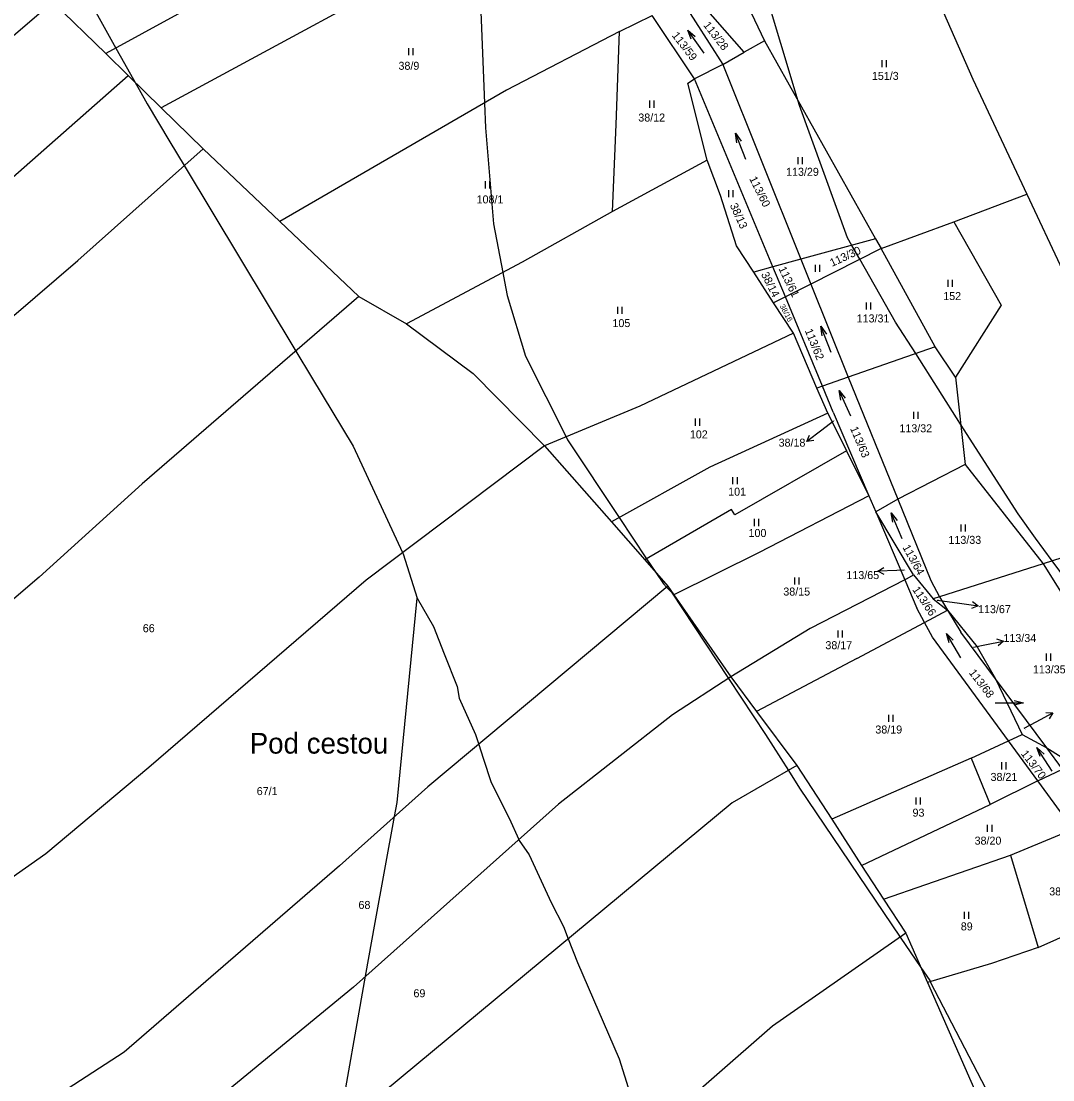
# Model space of a CAD drawing. Extents: x -749173 to -746119, y -1132678 to -1130338.
# Drawn here: x -747589.9 to -747370.7, y -1131323.7 to -1131098.8 of the extents above; entities that cross this region are included whole.
import ezdxf

# ---------------------------------------------------------------- set-up
doc = ezdxf.new("R2010")
doc.units = 0
for name, color, linetype in [('Vrstva 1', 7, 'Continuous'), ('Vrstva 15', 7, 'Continuous'), ('Vrstva 16', 7, 'Continuous'), ('Vrstva 18', 7, 'Continuous'), ('Vrstva 25', 7, 'Continuous'), ('Vrstva 52', 7, 'Continuous'), ('Vrstva 6', 7, 'Continuous')]:
    doc.layers.add(name, color=color, linetype=linetype)

msp = doc.modelspace()

# ---------------------------------------------------------------- linework, layer by layer
at = {"layer": 'Vrstva 1'}
for points in [[(-747407.71, -1131065.71), (-747387.68, -1131111.18)], [(-747583.1, -1131094.79), (-747571.91, -1131105.73)], [(-747449.55, -1131094.47), (-747440.84, -1131108.03)], [(-747446.81, -1131111.05), (-747455.83, -1131097.63)], [(-747571.91, -1131105.73), (-747567.13, -1131110.4)], [(-747440.84, -1131108.03), (-747424.22, -1131149.41)], [(-747567.13, -1131110.4), (-747560.11, -1131117.26)], [(-747430.18, -1131151.04), (-747446.81, -1131111.05)], [(-747387.68, -1131111.18), (-747376.22, -1131135.6)], [(-747560.11, -1131117.26), (-747551.23, -1131125.94)], [(-747551.23, -1131125.94), (-747534.94, -1131141.41)], [(-747376.22, -1131135.6), (-747368.67, -1131151.69)], [(-747534.94, -1131141.41), (-747518.15, -1131157.34)], [(-747424.22, -1131149.41), (-747422.11, -1131154.66)], [(-747427.53, -1131157.41), (-747430.18, -1131151.04)], [(-747422.11, -1131154.66), (-747414.16, -1131174.44)], [(-747518.15, -1131157.34), (-747508, -1131163.09)], [(-747419.66, -1131176.34), (-747427.53, -1131157.41)], [(-747508, -1131163.09), (-747493.84, -1131173.69)], [(-747493.84, -1131173.69), (-747478.68, -1131189)], [(-747414.16, -1131174.44), (-747403.63, -1131200.37)], [(-747417.35, -1131181.9), (-747419.66, -1131176.34)], [(-747417.35, -1131181.9), (-747409.79, -1131199.63)], [(-747478.68, -1131189), (-747464.5, -1131205.17)], [(-747409.79, -1131199.63), (-747408.32, -1131203.08)], [(-747403.63, -1131200.37), (-747396.62, -1131217.65)], [(-747335.3, -1131202.07), (-747372.79, -1131214.07)], [(-747408.32, -1131203.08), (-747402.18, -1131217.46)], [(-747464.5, -1131205.17), (-747457.41, -1131213.25)], [(-747457.41, -1131213.25), (-747452.5, -1131218.84)], [(-747372.79, -1131214.07), (-747366.49, -1131224.14)], [(-747402.18, -1131217.46), (-747399.59, -1131223.53)], [(-747396.62, -1131217.65), (-747394.81, -1131221.1)], [(-747452.5, -1131218.84), (-747451.24, -1131220.66)], [(-747451.24, -1131220.66), (-747439.12, -1131238.12)], [(-747394.81, -1131221.1), (-747393.08, -1131223.94)], [(-747397.95, -1131226.54), (-747399.59, -1131223.53)], [(-747393.08, -1131223.94), (-747390.29, -1131228.61)], [(-747396.26, -1131229.64), (-747397.95, -1131226.54)], [(-747382.92, -1131238.52), (-747390.29, -1131228.61)], [(-747380.11, -1131251.72), (-747396.26, -1131229.64)], [(-747439.12, -1131238.12), (-747433.68, -1131245.43)], [(-747372.02, -1131253.19), (-747382.92, -1131238.52)], [(-747433.68, -1131245.43), (-747425.11, -1131256.95)], [(-747373.91, -1131260.21), (-747380.11, -1131251.72)], [(-747368.67, -1131257.7), (-747372.02, -1131253.19)], [(-747425.11, -1131256.95), (-747417.7, -1131268.35)], [(-747366.42, -1131270.45), (-747373.91, -1131260.21)], [(-747417.7, -1131268.35), (-747411.33, -1131278.16)], [(-747411.33, -1131278.16), (-747406.7, -1131285.28)], [(-747406.7, -1131285.28), (-747401.97, -1131292.55)], [(-747401.97, -1131292.55), (-747397.34, -1131303.04)], [(-747397.34, -1131303.04), (-747384.78, -1131331.55)]]:
    msp.add_lwpolyline(points, dxfattribs=at)
at = {"layer": 'Vrstva 16'}
for p, q in [((-747421.46, -1131187.91), (-747422.95, -1131188.12)), ((-747406.54, -1131216.37), (-747407.87, -1131215.68)), ((-747387.79, -1131222.09), (-747386.61, -1131223)), ((-747382.66, -1131230.03), (-747381.23, -1131230.49)), ((-747372.23, -1131245.7), (-747370.73, -1131245.76))]:
    msp.add_line(p, q, dxfattribs=at)
for points in [[(-747417.31, -1131183.76), (-747419.78, -1131185.67)], [(-747419.78, -1131185.67), (-747422.95, -1131188.12), (-747422.38, -1131186.73)], [(-747403.87, -1131215.51), (-747407.87, -1131215.68), (-747406.6, -1131214.87)], [(-747402.28, -1131215.44), (-747403.87, -1131215.51)], [(-747395.32, -1131221.83), (-747390.57, -1131222.47)], [(-747390.57, -1131222.47), (-747386.61, -1131223), (-747387.99, -1131223.57)], [(-747387.54, -1131231.81), (-747385.15, -1131231.31)], [(-747385.15, -1131231.31), (-747381.23, -1131230.49), (-747382.35, -1131231.49)], [(-747374.26, -1131247.63), (-747370.73, -1131245.76), (-747371.52, -1131247.03)], [(-747376.82, -1131248.99), (-747374.26, -1131247.63)]]:
    msp.add_lwpolyline(points, dxfattribs=at)
at = {"layer": 'Vrstva 25'}
for p, q in [((-747444.8, -1131105.64), (-747448.26, -1131100.74)), ((-747507.59, -1131104.59), (-747507.59, -1131106.09)), ((-747506.59, -1131106.09), (-747506.59, -1131104.59)), ((-747407.03, -1131107.11), (-747407.03, -1131108.61)), ((-747406.03, -1131108.61), (-747406.03, -1131107.11)), ((-747456.4, -1131115.71), (-747456.4, -1131117.21)), ((-747455.4, -1131117.21), (-747455.4, -1131115.71)), ((-747435.9, -1131128.23), (-747438.12, -1131122.65)), ((-747424.87, -1131127.73), (-747424.87, -1131129.23)), ((-747423.87, -1131129.23), (-747423.87, -1131127.73)), ((-747491.31, -1131132.85), (-747491.31, -1131134.35)), ((-747490.31, -1131134.35), (-747490.31, -1131132.85)), ((-747439.62, -1131134.7), (-747439.62, -1131136.2)), ((-747438.62, -1131136.2), (-747438.62, -1131134.7)), ((-747421.18, -1131150.59), (-747421.18, -1131152.09)), ((-747420.18, -1131152.09), (-747420.18, -1131150.59)), ((-747393, -1131153.76), (-747393, -1131155.26)), ((-747392, -1131155.26), (-747392, -1131153.76)), ((-747463.18, -1131159.49), (-747463.18, -1131160.99)), ((-747462.18, -1131160.99), (-747462.18, -1131159.49)), ((-747410.36, -1131158.56), (-747410.36, -1131160.06)), ((-747409.36, -1131160.06), (-747409.36, -1131158.56)), ((-747417.79, -1131169.24), (-747419.97, -1131163.64)), ((-747413.66, -1131182.76), (-747416.14, -1131177.3)), ((-747400.34, -1131181.78), (-747400.34, -1131183.28)), ((-747399.34, -1131183.28), (-747399.34, -1131181.78)), ((-747446.71, -1131183.25), (-747446.71, -1131184.75)), ((-747445.71, -1131184.75), (-747445.71, -1131183.25)), ((-747438.73, -1131195.67), (-747438.73, -1131197.17)), ((-747437.73, -1131197.17), (-747437.73, -1131195.67)), ((-747434.16, -1131204.56), (-747434.16, -1131206.06)), ((-747433.16, -1131206.06), (-747433.16, -1131204.56)), ((-747402.76, -1131208.77), (-747405.04, -1131203.23)), ((-747390.27, -1131205.71), (-747390.27, -1131207.21)), ((-747389.27, -1131207.21), (-747389.27, -1131205.71)), ((-747425.62, -1131217), (-747425.62, -1131218.5)), ((-747424.62, -1131218.5), (-747424.62, -1131217)), ((-747416.41, -1131228.27), (-747416.41, -1131229.77)), ((-747415.41, -1131229.77), (-747415.41, -1131228.27)), ((-747390.28, -1131234.03), (-747393.34, -1131228.87)), ((-747372.14, -1131233.16), (-747372.14, -1131234.66)), ((-747371.14, -1131234.66), (-747371.14, -1131233.16)), ((-747382.96, -1131243.6), (-747376.96, -1131243.6)), ((-747405.61, -1131246.17), (-747405.61, -1131247.67)), ((-747404.61, -1131247.67), (-747404.61, -1131246.17)), ((-747370.85, -1131258.13), (-747374.09, -1131253.07)), ((-747381.65, -1131256.25), (-747381.65, -1131257.75)), ((-747380.65, -1131257.75), (-747380.65, -1131256.25)), ((-747399.85, -1131263.7), (-747399.85, -1131265.2)), ((-747398.85, -1131265.2), (-747398.85, -1131263.7)), ((-747384.64, -1131269.52), (-747384.64, -1131271.02)), ((-747383.64, -1131271.02), (-747383.64, -1131269.52)), ((-747389.54, -1131287.99), (-747389.54, -1131289.49)), ((-747388.54, -1131289.49), (-747388.54, -1131287.99))]:
    msp.add_line(p, q, dxfattribs=at)
for points in [[(-747447.52, -1131102.66), (-747448.26, -1131100.74), (-747446.7, -1131102.08)], [(-747437.84, -1131124.7), (-747438.12, -1131122.65), (-747436.91, -1131124.33)], [(-747419.71, -1131165.69), (-747419.97, -1131163.64), (-747418.78, -1131165.33)], [(-747415.77, -1131179.33), (-747416.14, -1131177.3), (-747414.86, -1131178.91)], [(-747404.74, -1131205.27), (-747405.04, -1131203.23), (-747403.82, -1131204.89)], [(-747392.75, -1131230.85), (-747393.34, -1131228.87), (-747391.89, -1131230.33)], [(-747378.96, -1131243.1), (-747376.96, -1131243.6), (-747378.96, -1131244.1)], [(-747373.43, -1131255.03), (-747374.09, -1131253.07), (-747372.59, -1131254.49)]]:
    msp.add_lwpolyline(points, dxfattribs=at)
at = {"layer": 'Vrstva 52'}
for points in [[(-747492.89, -1131080.86), (-747491.46, -1131116.22), (-747491.25, -1131121.5), (-747489.56, -1131141.87), (-747487.57, -1131152.24), (-747487.21, -1131154.11), (-747486.62, -1131157.12), (-747482.75, -1131170), (-747474.13, -1131187.11), (-747473.81, -1131187.75), (-747462.84, -1131204.25), (-747457, -1131213.01), (-747455.08, -1131215.9), (-747453.44, -1131218.37), (-747452.77, -1131219.06), (-747451.75, -1131220.12), (-747439.63, -1131238.45), (-747431.75, -1131250.37), (-747426.9, -1131257.98), (-747424.5, -1131261.75), (-747403.13, -1131293.36), (-747398.74, -1131299.86), (-747396.87, -1131302.62), (-747396.75, -1131302.86), (-747384.94, -1131325.62)], [(-747577.22, -1131091.12), (-747569.73, -1131104.54), (-747567.91, -1131107.81), (-747565.66, -1131111.84), (-747564.82, -1131113.33), (-747563.12, -1131116.37), (-747558.25, -1131124.47), (-747555.23, -1131129.51), (-747531.54, -1131168.9), (-747528.2, -1131174.44), (-747519.37, -1131189.12), (-747508.83, -1131211.69), (-747508.69, -1131212), (-747505.75, -1131221.37)], [(-747368.81, -1131216.25), (-747370.86, -1131213.45), (-747374.37, -1131208.64), (-747378.12, -1131203.5), (-747390.3, -1131184.42), (-747399.85, -1131169.45), (-747404.12, -1131162.75), (-747411.72, -1131149.41), (-747413.41, -1131146.45), (-747414.31, -1131144.87), (-747424.5, -1131116.75), (-747424.79, -1131115.8), (-747432.19, -1131091.25)], [(-747522.43, -1131334.23), (-747516.7, -1131301.69), (-747514.69, -1131290.25), (-747510.56, -1131267.78), (-747510, -1131264.75), (-747505.75, -1131221.37)], [(-747505.75, -1131221.37), (-747502.31, -1131227.37), (-747500, -1131233.2), (-747497.25, -1131240.12), (-747496.81, -1131242.62), (-747493.37, -1131250.37), (-747492.68, -1131252.43), (-747491.69, -1131255.37), (-747490, -1131260.5), (-747486.19, -1131268.12), (-747484.17, -1131272.64), (-747484.12, -1131272.74), (-747484.06, -1131272.87), (-747481.94, -1131275.87), (-747477.25, -1131286), (-747474.69, -1131291.12), (-747473.65, -1131293.76), (-747471.69, -1131298.75), (-747462.81, -1131319.25), (-747457.56, -1131336.16)]]:
    msp.add_lwpolyline(points, dxfattribs=at)
at = {"layer": 'Vrstva 6'}
for points in [[(-747519.1, -1131076.81), (-747571.91, -1131105.73)], [(-747493.05, -1131080.92), (-747560.11, -1131117.26)], [(-747437.65, -1131091.07), (-747431.95, -1131103.02)], [(-747436.27, -1131105.41), (-747447.06, -1131093.1)], [(-747583.1, -1131094.79), (-747617.7, -1131124.35)], [(-747462.74, -1131101.03), (-747455.83, -1131097.63)], [(-747462.74, -1131101.03), (-747486.76, -1131113.5)], [(-747463.44, -1131120.77), (-747462.74, -1131101.03)], [(-747431.95, -1131103.02), (-747436.27, -1131105.41)], [(-747431.95, -1131103.02), (-747408.38, -1131145.07)], [(-747440.84, -1131108.03), (-747436.27, -1131105.41)], [(-747440.84, -1131108.03), (-747446.81, -1131111.05)], [(-747620.97, -1131157.74), (-747567.13, -1131110.4)], [(-747448.25, -1131112.03), (-747446.81, -1131111.05)], [(-747444.14, -1131128.36), (-747448.25, -1131112.03)], [(-747486.76, -1131113.5), (-747534.94, -1131141.41)], [(-747464.26, -1131139.24), (-747463.44, -1131120.77)], [(-747577.82, -1131149.69), (-747551.23, -1131125.94)], [(-747444.14, -1131128.36), (-747464.26, -1131139.24)], [(-747441.29, -1131135.89), (-747444.14, -1131128.36)], [(-747437.88, -1131146.58), (-747441.29, -1131135.89)], [(-747391.74, -1131141.48), (-747376.22, -1131135.6)], [(-747464.26, -1131139.24), (-747483.41, -1131150.03)], [(-747407.22, -1131147.14), (-747391.74, -1131141.48)], [(-747391.74, -1131141.48), (-747381.7, -1131159.18)], [(-747408.38, -1131145.07), (-747424.22, -1131149.41)], [(-747408.38, -1131145.07), (-747407.22, -1131147.14)], [(-747434.26, -1131152.16), (-747437.88, -1131146.58)], [(-747407.22, -1131147.14), (-747422.11, -1131154.66)], [(-747395.7, -1131168), (-747407.22, -1131147.14)], [(-747622.68, -1131188.16), (-747577.82, -1131149.69)], [(-747483.41, -1131150.03), (-747508, -1131163.09)], [(-747424.22, -1131149.41), (-747430.18, -1131151.04)], [(-747430.18, -1131151.04), (-747434.26, -1131152.16)], [(-747430.03, -1131158.67), (-747434.26, -1131152.16)], [(-747422.11, -1131154.66), (-747427.53, -1131157.41)], [(-747518.15, -1131157.34), (-747564.17, -1131197.09)], [(-747427.53, -1131157.41), (-747430.03, -1131158.67)], [(-747425.84, -1131165.11), (-747430.03, -1131158.67)], [(-747381.7, -1131159.18), (-747391.42, -1131174.47)], [(-747425.84, -1131165.11), (-747458.47, -1131180.59)], [(-747420.83, -1131176.75), (-747425.84, -1131165.11)], [(-747395.7, -1131168), (-747414.16, -1131174.44)], [(-747391.42, -1131174.47), (-747395.7, -1131168)], [(-747414.16, -1131174.44), (-747419.66, -1131176.34)], [(-747391.42, -1131174.47), (-747389.33, -1131193.02)], [(-747419.66, -1131176.34), (-747420.83, -1131176.75)], [(-747418.53, -1131182.09), (-747420.83, -1131176.75)], [(-747458.47, -1131180.59), (-747478.68, -1131189)], [(-747418.53, -1131182.09), (-747443.59, -1131193.55)], [(-747418.53, -1131182.09), (-747414.55, -1131190.08)], [(-747478.68, -1131189), (-747516.61, -1131217.55)], [(-747414.55, -1131190.08), (-747438.27, -1131203.66)], [(-747414.55, -1131190.08), (-747409.79, -1131199.63)], [(-747389.33, -1131193.02), (-747403.63, -1131200.37)], [(-747389.33, -1131193.02), (-747372.79, -1131214.07)], [(-747443.59, -1131193.55), (-747464.5, -1131205.17)], [(-747564.17, -1131197.09), (-747586.04, -1131216.89)], [(-747409.79, -1131199.63), (-747433.07, -1131211.69)], [(-747403.63, -1131200.37), (-747408.32, -1131203.08)], [(-747438.96, -1131202.58), (-747457.41, -1131213.25)], [(-747438.27, -1131203.66), (-747438.96, -1131202.58)], [(-747400.3, -1131216.43), (-747408.32, -1131203.08)], [(-747433.07, -1131211.69), (-747451.24, -1131220.66)], [(-747372.79, -1131214.07), (-747394.81, -1131221.1)], [(-747586.04, -1131216.89), (-747605.36, -1131233.4)], [(-747516.61, -1131217.55), (-747562.75, -1131257.36)], [(-747402.18, -1131217.46), (-747422.3, -1131227.8)], [(-747402.18, -1131217.46), (-747400.3, -1131216.43)], [(-747400.3, -1131216.43), (-747396.13, -1131221.54)], [(-747452.5, -1131218.84), (-747503.48, -1131261.46)], [(-747394.81, -1131221.1), (-747396.13, -1131221.54)], [(-747396.13, -1131221.54), (-747393.08, -1131223.94)], [(-747397.95, -1131226.54), (-747393.08, -1131223.94)], [(-747393.08, -1131223.94), (-747386.77, -1131231.73)], [(-747412.33, -1131234.19), (-747397.95, -1131226.54)], [(-747422.3, -1131227.8), (-747439.12, -1131238.12)], [(-747386.77, -1131231.73), (-747382.92, -1131238.52)], [(-747412.33, -1131234.19), (-747433.68, -1131245.43)], [(-747439.12, -1131238.12), (-747451.48, -1131246.17)], [(-747382.92, -1131238.52), (-747377.23, -1131250.36)], [(-747451.48, -1131246.17), (-747475.75, -1131265.13)], [(-747388.07, -1131255.34), (-747380.11, -1131251.72)], [(-747380.11, -1131251.72), (-747377.23, -1131250.36)], [(-747377.23, -1131250.36), (-747372.02, -1131253.19)], [(-747372.02, -1131253.19), (-747366.48, -1131256.66)], [(-747388.07, -1131255.34), (-747417.7, -1131268.35)], [(-747388.07, -1131255.34), (-747384.01, -1131265.18)], [(-747562.75, -1131257.36), (-747584.62, -1131275.69)], [(-747425.11, -1131256.95), (-747438.82, -1131264.87)], [(-747373.91, -1131260.21), (-747368.67, -1131257.7)], [(-747373.91, -1131260.21), (-747384.01, -1131265.18)], [(-747503.48, -1131261.46), (-747522.26, -1131278.21)], [(-747438.82, -1131264.87), (-747532.83, -1131342.86)], [(-747475.75, -1131265.13), (-747519.29, -1131304)], [(-747411.33, -1131278.16), (-747384.01, -1131265.18)], [(-747379.74, -1131275.95), (-747366.42, -1131270.45)], [(-747584.62, -1131275.69), (-747613.72, -1131296.16)], [(-747406.7, -1131285.28), (-747379.74, -1131275.95)], [(-747379.74, -1131275.95), (-747373.86, -1131295.58)], [(-747522.26, -1131278.21), (-747567.99, -1131317.8)], [(-747373.86, -1131295.58), (-747354.67, -1131286.99)], [(-747401.97, -1131292.55), (-747430.3, -1131312.29)], [(-747373.86, -1131295.58), (-747383.75, -1131299)], [(-747383.75, -1131299), (-747397.34, -1131303.04)], [(-747519.29, -1131304), (-747573.75, -1131348.78)], [(-747430.3, -1131312.29), (-747480.38, -1131356.14)], [(-747567.99, -1131317.8), (-747587.97, -1131330.74)]]:
    msp.add_lwpolyline(points, dxfattribs=at)

# ---------------------------------------------------------------- texts
at = {"layer": 'Vrstva 15'}
msp.add_text('Pod cestou', height=4.4, dxfattribs=at).set_placement((-747541.32, -1131254.4))
at = {"layer": 'Vrstva 16'}
for s, p in [('38/18', (-747428.97, -1131189.2)), ('113/65', (-747414.57, -1131217.33)), ('113/67', (-747386.6, -1131224.57)), ('113/34', (-747381.21, -1131230.7))]:
    msp.add_text(s, height=1.7, dxfattribs=at).set_placement(p)
at = {"layer": 'Vrstva 18'}
for s, height, rotation, p in [('113/59', 1.7, 307.7079, (-747451.73, -1131101.9)), ('113/28', 1.7, 307.7684, (-747445.05, -1131099.72)), ('113/60', 1.7, 296.565, (-747435.26, -1131132.29)), ('38/13', 1.7, 294.3625, (-747439.37, -1131137.93)), ('113/30', 1.7, 24.8874, (-747417.61, -1131151.03)), ('38/14', 1.7, 296.565, (-747432.74, -1131152.58)), ('113/61', 1.7, 295.6768, (-747429.03, -1131151.4)), ('38/16', 1.14, 297.7357, (-747428.77, -1131159.33)), ('113/62', 1.7, 292.1664, (-747423.44, -1131164.55)), ('113/63', 1.7, 292.8336, (-747413.82, -1131185.32)), ('113/64', 1.7, 298.794, (-747402.71, -1131210.58)), ('113/66', 1.7, 303.5589, (-747400.63, -1131219.57)), ('113/68', 1.7, 307.53, (-747388.64, -1131237.25)), ('113/69', 0.1, 304.0459, (-747376.82, -1131248.99)), ('113/70', 1.7, 307.2278, (-747377.58, -1131254.45))]:
    msp.add_text(s, height=height, rotation=rotation, dxfattribs=at).set_placement(p)
for s, height, p in [('38/9', 1.7, (-747509.71, -1131109.16)), ('151/3', 1.7, (-747409.16, -1131111.31)), ('38/12', 1.7, (-747458.77, -1131120.15)), ('113/29', 1.7, (-747427.38, -1131131.68)), ('108/1', 1.7, (-747493.12, -1131137.54)), ('152', 1.7, (-747394, -1131158.07)), ('113/31', 1.7, (-747412.39, -1131162.82)), ('105', 1.7, (-747464.26, -1131163.81)), ('38/18', 0.1, (-747417.31, -1131183.76)), ('113/32', 1.7, (-747403.31, -1131186.16)), ('102', 1.7, (-747447.82, -1131187.45)), ('101', 1.7, (-747439.68, -1131199.62)), ('100', 1.7, (-747435.36, -1131208.39)), ('113/33', 1.7, (-747392.89, -1131209.85)), ('113/65', 0.1, (-747402.48, -1131215.44)), ('38/15', 1.7, (-747427.97, -1131220.83)), ('113/67', 0.1, (-747395.32, -1131221.83)), ('66', 1.7, (-747564.03, -1131228.62)), ('38/17', 1.7, (-747419.03, -1131232.22)), ('113/34', 0.1, (-747387.54, -1131231.81)), ('113/35', 1.7, (-747374.96, -1131237.36)), ('38/19', 1.7, (-747408.42, -1131250.13)), ('38/21', 1.7, (-747383.95, -1131260.2)), ('67/1', 1.7, (-747539.82, -1131263.21)), ('93', 1.7, (-747400.52, -1131267.79)), ('38/20', 1.7, (-747387.34, -1131273.73)), ('38/22', 1.7, (-747371.49, -1131284.52)), ('68', 1.7, (-747518.21, -1131287.39)), ('89', 1.7, (-747390.27, -1131291.95)), ('69', 1.7, (-747506.53, -1131306.15))]:
    msp.add_text(s, height=height, dxfattribs=at).set_placement(p)

doc.saveas('drawing.dxf')
